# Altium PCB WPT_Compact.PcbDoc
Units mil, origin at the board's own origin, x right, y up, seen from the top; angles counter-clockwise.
Board outline 6000 x 4000 mil, 2 copper layers (Top Layer, Bottom Layer); 31 components, 24 nets, 101 pads, 11 vias.
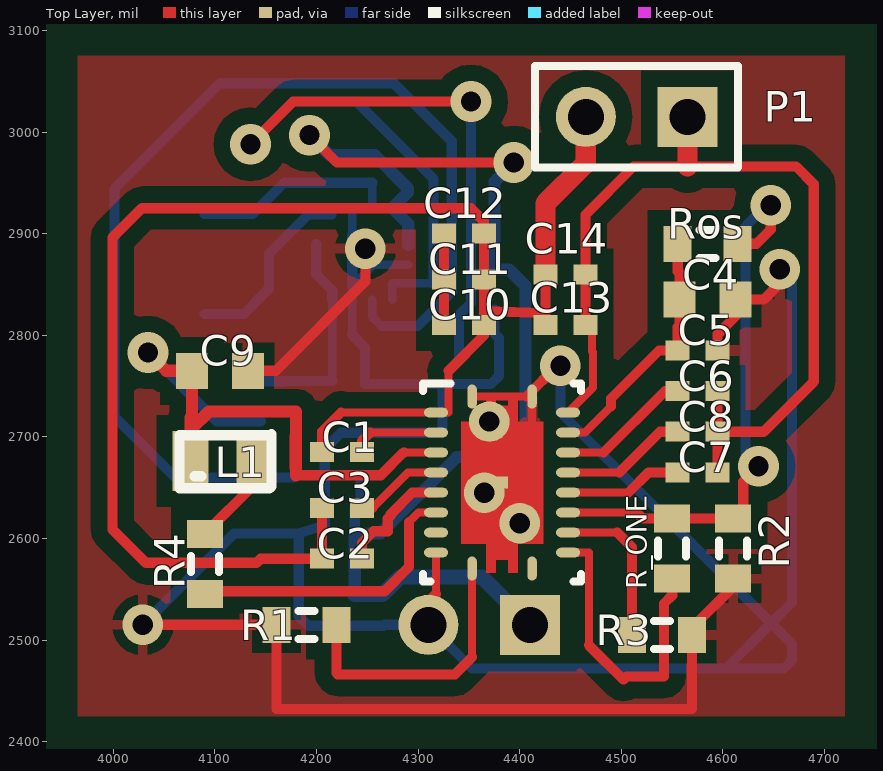
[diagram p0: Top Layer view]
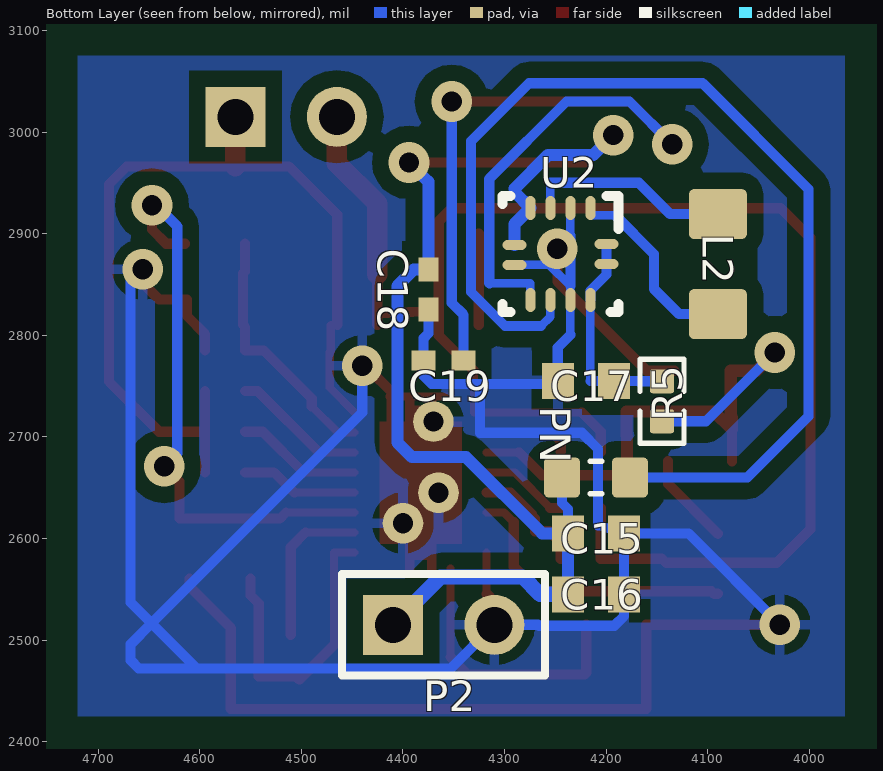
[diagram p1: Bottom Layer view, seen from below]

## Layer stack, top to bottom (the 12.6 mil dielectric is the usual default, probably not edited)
Top Solder: solder mask 0.4, Solder Resist, Dk 3.5
Top Layer: signal copper 1.4
Dielectric 1: dielectric 12.6, FR-4, Dk 4.8
Bottom Layer: signal copper 1.4
Bottom Solder: solder mask 0.4, Solder Resist, Dk 3.5

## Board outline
1000,1000 7000,1000 7000,5000 1000,5000

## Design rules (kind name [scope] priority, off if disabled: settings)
Clearance Clearance_GND [InPolygon] p1: gap=16
Clearance [All] p2: gap=8
PolygonConnect [All] p1: connectstyle=Relief reliefconductorwidth=10 reliefentries=4 polygonreliefangle="90 Angle" airgapwidth=10
RoutingVias [All] p1: holewidth=20 width=40 viastyle="Through Hole" minholewidth=20 minwidth=40 maxholewidth=20 maxwidth=40
SMDNeckDown [All] p1: percent=85.000
SolderMaskExpansion [All] p1: expansion=4
Width [All] p1: maxlimit=40 minlimit=8 preferedwidth=10 minimp=50.000000 maximp=50.000000 favimp=50.000000
30 further rules are at their usual default settings.

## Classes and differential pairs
component class BAT_Regulator: C15 C16 C17 C18 C19 L2 P2 R5 U2
component class WPT_Rx: C1 C2 C3 C4 C5 C6 C7 C8 C9 C10 C11 C12 C13 C14 L1 P2 R1 R2 R3 R4 R_ONE Ros

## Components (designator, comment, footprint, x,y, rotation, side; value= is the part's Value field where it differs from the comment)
C1 "0.01uF" 0402 4225,2685 r0 top
C2 "0.022uF" 0402 4225,2580 r180 top
C3 "0.47uF" 0402 4225,2630 r180 top
C4 "4.7uF" 1608[0603] 4585,2835 r0 top
C5 "0.022uF" 0402 4575,2785 r0 top
C6 "0.01uF" 0402 4575,2745 r180 top
C7 "0.022uF" 0402 4575,2665 r0 top
C8 "0.47uF" 0402 4575,2705 r0 top
C9 "4.7uF" 1608[0603] 4105,2765 r0 top
C10 "68nF" 0402 4345,2810 r180 top
C11 "68nF" 0402 4345,2855 r180 top
C12 "82nF" 0402 4345,2900 r180 top
C13 "2.2nF" 0402 4445,2810 r180 top
C14 "1nF" 0402 4445,2860 r180 top
C15 "10uF" 1608[0603] 4210,2605 r0 bottom
C16 "10uF" 1608[0603] 4210,2545 r0 bottom
C17 "10uF" 1608[0603] 4220,2755 r180 bottom
C18 "10pF" 0402 4375,2845 r90 bottom
C19 "1nF" 0402 4360,2775 r180 bottom
L1 "LED_0603" LED_0603 4075,2675 r0 top
L2 "1.5uH" INDM2520X190N 4090,2870 r90 bottom
P1 "Header 2" HDR1X2 4565,3015 r180 top (schematic designator P2)
P2 "Header 2" HDR1X2 4410,2515 r180 bottom (schematic designator P1)
R1 "2.4K" J1-0603 4190,2515 r180 top
R2 "140" J1-0603 4610,2590 r90 top
R3 "10k" J1-0603 4540,2505 r0 top
R4 "91" J1-0603 4090,2575 r90 top
R5 "0" RESC1005X40N 4145,2735 r90 bottom
R_ONE "470" J1-0603 4550,2590 r270 top
Ros "100K" J1-0603 4585,2890 r180 top
U2 "TPS63051RMWR" RMW0012A 4245,2880 r270 bottom

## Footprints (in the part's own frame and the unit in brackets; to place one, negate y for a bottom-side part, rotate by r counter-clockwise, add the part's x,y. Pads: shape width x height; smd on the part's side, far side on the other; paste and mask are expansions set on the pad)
0402 [mm] "Chip Capacitor, Body 1.0x0.5mm, IPC High Density"
  rect 0.6x0.5 smd: 1(-0.5,0) 2(0.5,0)
  body extent -0.55,-0.3 0.55,0.3, height 1.3
1608[0603] [mm] "Chip Capacitor, Body 1.6x0.8mm, IPC High Density"
  rect 0.8x0.9 smd: 1(-0.7,0) 2(0.7,0)
  body extent -0.87,-0.48 0.87,0.48, height 1.3
HDR1X2 [mm] "Connector; Header; 2 Position"
  rect 1.5x1.5 hole 0.9: 1(0,0)
  round 1.5 hole 0.9: 2(2.54,0)
  silkscreen extent -1.27,-1.27 3.81,1.27
INDM2520X190N [mm] "Inductor, molded body 2.5x2.0mm"
  round 0.508 on Mech15: 0(0,0)
  rrect20% 1.25x1.45 smd: 1(-1.25,0) 2(1.25,0)
  Top Layer pour cut-out: -0.7,1 0.7,1 0.7,-1 -0.7,-1
  body extent -1.25,-1 1.25,1, height 1.79
J1-0603 [mm] "Chip Resistor, Body 1.6x0.8mm, IPC High Density"
  rect 0.7x0.9 smd: 1(-0.75,0) 2(0.75,0)
  silkscreen extent -0.2,-0.35 0.2,0.35, body extent -0.85,-0.48 0.85,0.48, height 0.9
LED_0603 [mm] "LR Q396"
  rect 0.9x1.5 smd: 1(0.025,0.025) 2(1.625,0.025)
  silkscreen extent -0.25,-0.65 2.05,0.7
RESC1005X40N [mm] "Chip Resistor, Body 1.0x0.5mm, EIA 0402, IPC Medium Density"
  round 0.2 on Mech15: 0(0,0)
  rrect20% 0.6x0.6 smd: 1(-0.5,0) 2(0.5,0)
  Top Layer pour cut-out: -0.325,0.375 -0.2,0.5 0.2,0.5 0.325,0.375 0.325,-0.375 0.2,-0.5 -0.2,-0.5 -0.325,-0.375
  silkscreen extent -1.05,-0.55 1.05,0.55, body extent -0.52,-0.27 0.53,0.28, height 0.4
RMW0012A [mm]
  oval 0.6x0.25 smd paste+0 mask+0.051: 1(-1.15,0.75) 2(-1.15,0.25) 3(-1.15,-0.25) 4(-1.15,-0.75) 7(1.15,-0.75) 8(1.15,-0.25) 9(1.15,0.25) 10(1.15,0.75)
  oval 0.25x0.6 smd paste+0 mask+0.051: 5(-0.225,-1.15) 6(0.275,-1.15) 11(0.25,1.15) 12(-0.25,1.15)
  silkscreen extent -1.45,-1.45 1.45,1.45, body extent 0,0 0.25,0.25, height 0.25

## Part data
C1 C2 C3 C4 C5 C6 C7 C8 C9 C10 C11 C12 C13 C14 C15 C16 C17 C18 C19: library part "Cap Semi", "Capacitor (Semiconductor SIM Model)"
L2: library part INDC_47n_1008_1A, "Inductor SMD chip 47nH 1008"
P1 P2: "Header, 2-Pin"
R1 R2 R3 R4 R_ONE Ros: library part Res3, "Resistor"
R5: library part RES_1K_0402_5%, "Resistor SMD chip 1k Ohm 0.063W 5% 0402"
U2: "Imported"

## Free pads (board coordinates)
  round 10 on Mech15: 0(4210,2660)
  rrect25% 35.43x39.37 smd far side: 1(4243.46,2660) 2(4176.54,2660)
  oval 9.45x23.62 smd paste-4 mask+2: 1(4353.03,2739.65) 10(4353.03,2570.35) 11(4412.09,2570.35) 20(4412.09,2739.65)
  oval 23.62x9.45 smd paste-4 mask+2: 2(4317.6,2723.89) 3(4317.6,2704.21) 4(4317.6,2684.52) 5(4317.6,2664.84) 6(4317.6,2645.15) 7(4317.6,2625.47) 8(4317.6,2605.78) 9(4317.6,2586.1) 12(4447.52,2586.1) 13(4447.52,2605.78) 14(4447.52,2625.47) 15(4447.52,2645.15) 16(4447.52,2664.84) 17(4447.52,2684.52) 18(4447.52,2704.21) 19(4447.52,2723.89)
  rect 11.81x11.81 smd paste-5.41 mask+0: 21(4382.56,2655)
  round 40 / inner round 60 / far side round 40 hole 20 mask+2: V(4365,2645) V(4370,2715) V(4400,2615)

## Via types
v1: diameter 40, hole 20, Top Layer to Bottom Layer, 11 vias

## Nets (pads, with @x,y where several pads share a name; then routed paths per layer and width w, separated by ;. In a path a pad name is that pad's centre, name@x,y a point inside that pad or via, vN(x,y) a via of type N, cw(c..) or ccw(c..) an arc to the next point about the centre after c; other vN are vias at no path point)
AC1: C1.1 C2.2 C3.2 C10.1 C11.1 C12.1 C13.2 C14.2 P1.2 pad.2@4317.6,2723.89 | length 1579.1
  Top Layer w8.03: 4224,2723.89 4317.6,2723.89 4330,2723.89 4330,2765
  Top Layer w10: C3.2 C2.2 4145,2580 4141,2576 4032,2576 3999,2609 3999,2896 4028,2925 4352,2925 4364.69,2912.31 C12.1 C11.1 4364.69,2824 ; C1.1 4205.32,2705.21 4224,2723.89 ; 4330,2765 4364.69,2799.69 C10.1 4364.69,2824 ; C13.2 4425.31,2821.69 ; C14.2 4425.31,2821.69 ; 4364.69,2824 4365.22,2823.98 4425.31,2821.69
  Top Layer w20: C14.2 4425.31,2929.69 4465,2969.37 P1.2
AC2: C6.1 C7.2 C8.2 C13.1 C14.1 P1.1 pad.19 | length 901.5
  Top Layer w8.03: pad.19 4472.02,2748.39 4472.02,2783.26 4471.02,2784.26 4471.02,2810 C13.1
  Top Layer w10: C13.1 C14.1 4464.69,2918.69 4512,2966 4565,2966 4672,2966 4689.31,2948.69 4689.31,2754.31 4640,2705 C8.2 ; C7.2 C8.2 ; C6.1 C8.2
  Top Layer w20: 4565,2966 P1.1
FOD: pad.14 R2.2 R_ONE.1 Ros.1 | length 569.9
  Top Layer w8.03: pad.14 4515.06,2625.47
  Top Layer w10: 4515.06,2625.47 4521,2619.53 R_ONE.1 R2.2 4620,2619.53 4620,2656 v1(4635,2671) ; Ros.1 4633,2890 4647,2904 v1(4647,2928)
  Bottom Layer w10: v1(4635,2671) 4622.15,2683.85 4622.15,2907.15 4643,2928 v1(4647,2928)
GND: C4.2 C5.2 C9.2 C15.1 C16.1 C17.1 C18.1 C19.1 P2.2 pad.1@4353.03,2739.65 pad.9 pad.20 pad.21 pad.V R1.2 R2.1 R3.2 U2.2 U2.6 U2.9 | length 3686.7
  Top Layer w8.03: 4317.6,2545.41 pad.9 ; pad.1@4353.03,2739.65 4406.65,2739.65 ; 4412.09,2694 pad.20
  Top Layer w10: v1(4029,2515) R1.2 4160.47,2432 4569.53,2432 R3.2 4569.53,2512 4610,2552.47 R2.1 ; C9.2 4160,2765 4248,2853 v1(4248,2885) ; P2.2 4310,2537.82 4317.6,2545.41 ; pad.21 4382.56,2664.47 ; pad.20 4406.65,2739.65 4437,2770 v1(4440,2770) ; C5.2 4594.69,2801 4612.56,2818.87 C4.2 4640,2835 4656,2851 v1(4656,2865)
  Top Layer w12: 4382.56,2664.47 4412.09,2694
  Bottom Layer w8.37: 4235.16,2800.4 U2.9 4235.16,2848.33 4256,2869.17 U2.6 ; v1@4235.16,2897.84 U2.2
  Bottom Layer w10: v1(4029,2515) 4119,2605 C15.1 ; 4235.16,2800.4 4247.56,2788 C17.1 4247.56,2752 4324,2752 ; 4235.16,2848.33 4235.16,2897.84 v1(4248,2885) ; C18.1 4375,2801.69 4379.69,2797 C19.1 4379.69,2760 4371.69,2752 4324,2752 ; v1(4440,2770) 4434,2770 4440,2764 4440,2724 4647.5,2516.5 ; v1(4656,2865) 4668,2853 4668,2537 4647.5,2516.5 ; C15.1 C16.1 4182.44,2523.56 4192,2514 4266,2514 4267,2515 P2.2 4353,2472 4603,2472 ; C15.1 4208,2613 4208,2688 4224,2704 4324,2704 4324,2752 ; 4603,2472 4660,2472 4668,2480 4668,2496 4647.5,2516.5 ; 4603,2472 4647.5,2516.5
NetC1_2: C1.2 pad.3 | length 87.3
  Top Layer w8.03: 4252.9,2704.21 pad.3
  Top Layer w10: C1.2 4244.69,2696 4252.9,2704.21
NetC2_1: C2.1 pad.6 | length 117.3
  Top Layer w10: C2.1 4244.69,2595.69 4256,2607 4270,2607 4270,2619.54 4273,2622.54 4273,2623.94 4294.22,2645.15 pad.6
NetC3_1: C3.1 pad.5 | length 87.3
  Top Layer w8.03: C3.1@4255,2630 4289.84,2664.84 pad.5
  Top Layer w10: C3.1 C3.1@4255,2630
NetC4_1: C4.1 C5.1 pad.18 Ros.2 | length 252.5
  Top Layer w8.03: pad.18 4464,2704.21 4489.73,2729.94
  Top Layer w10: 4489.73,2729.94 4489.73,2737.73 4537,2785 C5.1 4555.32,2808 4557.44,2810.13 C4.1 4557.44,2861 4555.47,2862.97 Ros.2
NetC6_2: C6.2 pad.17 | length 132.8
  Top Layer w8.03: pad.17 4482.45,2684.52
  Top Layer w10: 4482.45,2684.52 4542.93,2745 C6.2
NetC7_1: C7.1 pad.15 | length 116
  Top Layer w8.03: pad.15 4507,2645.15
  Top Layer w10: 4507,2645.15 4526.85,2665 C7.1
NetC8_1: C8.1 pad.16 | length 124.4
  Top Layer w8.03: pad.16 4497.84,2664.84
  Top Layer w10: 4497.84,2664.84 4538,2705 C8.1
NetC9_1: C9.1 L1.1 pad.4 R5.1 | length 601
  Top Layer w8.03: 4286.46,2684.52 pad.4
  Top Layer w10: L1.1 4075.98,2706.98 ; 4075.98,2719 4077.44,2720.46 ; 4179.84,2662.16 4263.09,2662.16 4285.46,2684.52 4286.46,2684.52
  Top Layer w12: v1(4034,2783) 4052,2765 C9.1 4077.44,2720.46 ; 4075.98,2719 4075.98,2706.98 4094,2725 4179.84,2725 4179.84,2700.98 4179.51,2700.64 4179.51,2669.36 4179.84,2669.02 4179.84,2662.16
  Bottom Layer w10: v1(4034,2783) 4101.68,2715.32 R5.1
NetC10_2: C10.2 C11.2 C12.2 | length 90
  Top Layer w10: C10.2 C11.2 C12.2
NetC15_2: C15.2 C16.2 C18.2 P2.1 pad.1@4243.46,2660 U2.4 U2.5 | length 1225.3
  Top Layer w10: v1(4193,2997) 4220,2970 v1(4394,2970)
  Bottom Layer w8.37: 4290,2940.75 4290,2944.53
  Bottom Layer w10: C15.2 4237.56,2629 4243.46,2634.9 pad.1@4243.46,2660
  Bottom Layer w12: v1(4193,2997) 4212.74,2977.26 4257.26,2977.26 4290,2944.53 ; C16.2 C15.2 4263,2605 4338,2680 4391,2680 4405.5,2694.5 4405.5,2848.5 4389.31,2864.69 C18.2 4375,2951 v1(4394,2970) ; 4290,2940.75 U2.4 4290.28,2909.53 U2.5
  Bottom Layer w15: C16.2 4265,2545 4282,2562 4363,2562 P2.1
NetC17_2: C17.2 R5.2 U2.10 U2.11 U2.12 | length 212
  Bottom Layer w8.37: 4215.47,2755 U2.10
  Bottom Layer w10: R5.2 4168,2754.69 4168.31,2755 C17.2 4215.47,2755 ; U2.12 U2.11 4199.72,2859.75 4215.47,2844 U2.10
NetC19_2: C19.2 U2.7 | length 882.8
  Top Layer w10: v1(4135,2988) 4177,3030 v1(4352,3030)
  Bottom Layer w8.37: U2.7 4274.53,2851 4314.84,2851
  Bottom Layer w10: v1(4135,2988) 4177,3030 4239,3030 4315.09,2953.91 4315.09,2851.25 4314.84,2851 ; C19.2 4340.31,2820 4352,2831.69 v1(4352,3030)
NetL1_2: L1.2 R4.2 | length 91.7
  Top Layer w10: R4.2 4138.98,2653.5 L1.2
NetL2_1: L2.1 U2.1 | length 193.1
  Bottom Layer w8.37: 4191,2918 4215.47,2918 U2.1
  Bottom Layer w10: L2.1 4128,2820.79 4153,2845.79 4153,2880 4191,2918
NetL2_2: L2.2 U2.3 | length 202.4
  Bottom Layer w8.37: U2.3 4254.84,2950.09
  Bottom Layer w10: L2.2 4137,2919.21 4167.88,2950.09 4254.84,2950.09
NetR1_1: pad.10 R1.1 | length 275.9
  Top Layer w8.03: 4353.03,2483.14 pad.10
  Top Layer w10: R1.1 4219.53,2467.47 4220.9,2466.1 4336,2466.1 4353.03,2483.14
NetR3_1: pad.13 R3.1 | length 155.3
  Top Layer w8.03: pad.13 4496,2605.78
  Top Layer w10: 4496,2605.78 4510.47,2591.31 R3.1
NetR6_2: pad.2@4176.54,2660 U2.8 | length 1084
  Bottom Layer w8.37: U2.8 4254.84,2818.16 4264,2809
  Bottom Layer w10: pad.2@4176.54,2660 4061,2660 4001,2720 4001,2944 4105,3048 4276,3048 4333.09,2990.91 4333.09,2842.58 4299.5,2809 4264,2809
NetR_ONE_2: pad.12 R_ONE.2 | length 300.7
  Top Layer w8.03: pad.12 4468,2586.1 4468,2495
  Top Layer w10: 4468,2495 4502,2461 4505,2464 4542,2464 4542,2536 4550,2544 R_ONE.2
~CHG: pad.7 R4.1 | length 286.5
  Top Layer w8.03: 4291,2616 4300.47,2625.47 pad.7
  Top Layer w10: R4.1 4094,2545.47 4096.53,2548 4267,2548 4291,2572 4291,2616
pads on no net: L2.0 R5.0

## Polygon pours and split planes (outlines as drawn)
GND on Top Layer "DC_GND" (solid, pour order 0): 3965,3075 3965,2425 4720,2425 4720,3075
GND on Bottom Layer "DC_GND" (solid, pour order 6): 3965,3075 4720,3075 4720,2425 3965,2425

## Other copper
Top Layer:
  region net GND: 4397.92,2743.58 4388.86,2743.58 4388.86,2730.78 4376.26,2730.78 4376.26,2743.58 4367.21,2743.58 4367.21,2715.04 4342.21,2715.04 4342.21,2594.96 4367.21,2594.96 4367.21,2566.42 4376.26,2566.42 4376.26,2579.21 4388.86,2579.21 4388.86,2566.42 4397.92,2566.42 4397.92,2594.96 4422.92,2594.96 4422.92,2715.04 4397.92,2715.04
Bottom Layer:
  pour cut-out: 4233.62,2679.69 4225.75,2687.56 4194.25,2687.56 4186.38,2679.69 4186.38,2640.31 4194.25,2632.44 4225.75,2632.44 4233.62,2640.31

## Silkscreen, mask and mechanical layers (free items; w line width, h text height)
Top Overlay:
  lines w7.87: 4304.8,2564.85 4304.8,2557.56 4312.08,2557.56 ; 4304.81,2745.15 4304.81,2752.44 4331.77,2752.44 ; 4453.03,2557.56 4460.32,2557.56 4460.32,2564.85 ; 4453.03,2752.44 4460.32,2752.44 4460.32,2745.15
Bottom Overlay:
  lines w5: 4204,2644 4216,2644 ; 4204,2676 4216,2676
Top Paste:
  region: 4386.5,2651.06 4386.5,2598.78 4422.6,2598.78 4422.6,2651.06
  region: 4378.62,2598.78 4378.62,2651.06 4342.52,2651.06 4342.52,2598.78
  region: 4378.62,2658.94 4378.62,2711.22 4342.52,2711.22 4342.52,2658.94
  region: 4386.5,2711.22 4386.5,2658.94 4422.6,2658.94 4422.6,2711.22
  region: 4367.21,2730.79 4367.21,2719.09 4397.92,2719.09 4397.92,2730.79
  region: 4367.21,2590.91 4367.21,2579.21 4397.92,2579.21 4397.92,2590.91
Mechanical 13:
  circle w3.94: c4353.03,2724.88 r11.81
  lines w1.97: 4175.55,2641.3 4175.55,2678.7 4191.3,2678.7 4191.3,2641.3 4175.55,2641.3 ; 4191.3,2641.34 4228.7,2641.34 4191.3,2641.36 ; 4191.3,2678.66 4228.7,2678.64 4191.3,2678.66 ; 4228.7,2641.3 4228.7,2678.7 4244.45,2678.7 4244.45,2641.3 4228.7,2641.3
  lines w3.94: 4310.71,2563.46 4454.41,2563.46 4454.41,2746.53 4310.71,2746.53 4310.71,2563.46
  text ".Designator" at 4272.56,2785 h50
Mechanical 15:
  lines w3.94: 4150.94,2632.44 4269.06,2632.44 4269.06,2687.56 4150.94,2687.56 4150.94,2632.44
